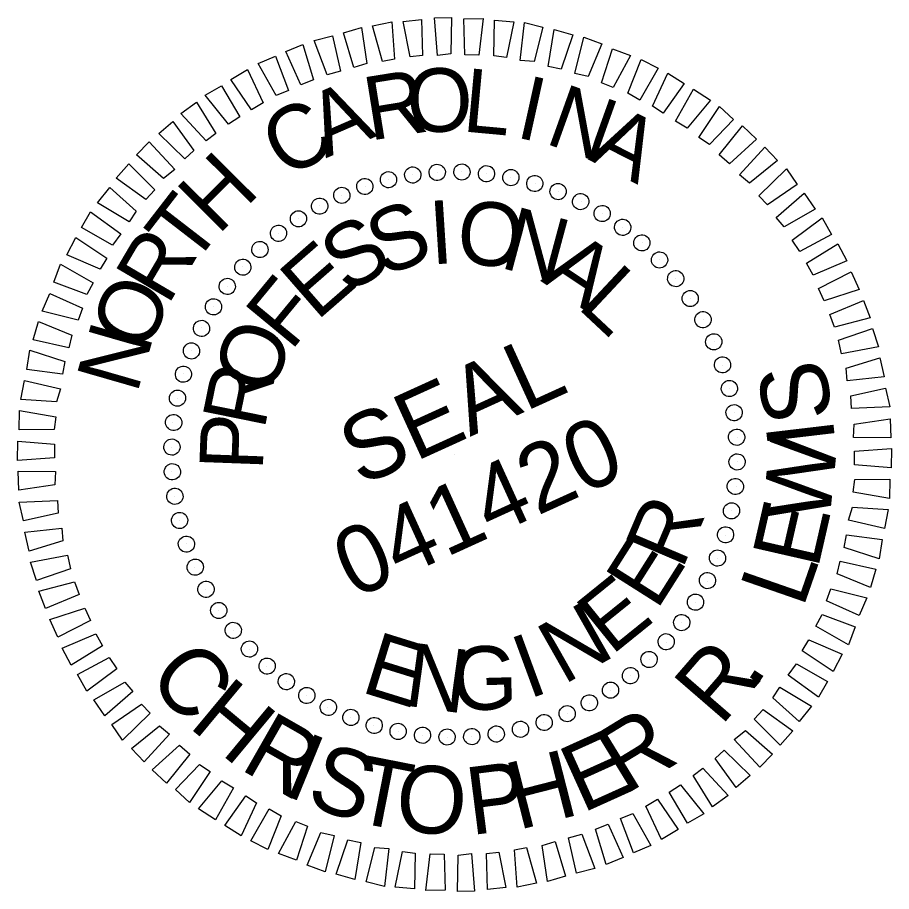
# Model space of a CAD drawing. Extents: x 2237908 to 2239894, y 658266 to 660035.
# Drawn here: x 2239756.3 to 2239833.9, y 659957.6 to 660035.2 of the extents above; entities that cross this region are included whole.
import ezdxf

# ---------------------------------------------------------------- set-up
doc = ezdxf.new("R2010")
doc.units = 0
doc.layers.add('Sheet PE Seal Cell', color=7, linetype='Continuous')

msp = doc.modelspace()

# ---------------------------------------------------------------- linework, layer by layer
at = {"layer": 'Sheet PE Seal Cell'}
for p, q in [((2239791.368, 660021.269), (2239791.368, 660021.269)), ((2239793.569, 660021.503), (2239793.569, 660021.503)), ((2239795.762, 660021.514), (2239795.762, 660021.514)), ((2239797.951, 660021.412), (2239797.951, 660021.412)), ((2239789.27, 660020.808), (2239789.27, 660020.808)), ((2239800.108, 660021.021), (2239800.108, 660021.021)), ((2239802.26, 660020.518), (2239802.26, 660020.518)), ((2239787.169, 660020.235), (2239787.169, 660020.235)), ((2239804.292, 660019.796), (2239804.292, 660019.796)), ((2239785.105, 660019.459), (2239785.105, 660019.459)), ((2239806.341, 660018.917), (2239806.341, 660018.917)), ((2239783.123, 660018.502), (2239783.123, 660018.502)), ((2239781.291, 660017.337), (2239781.291, 660017.337)), ((2239808.205, 660017.842), (2239808.205, 660017.842)), ((2239810.039, 660016.59), (2239810.039, 660016.59)), ((2239779.455, 660016.061), (2239779.455, 660016.061)), ((2239811.758, 660015.231), (2239811.758, 660015.231)), ((2239777.793, 660014.644), (2239777.793, 660014.644)), ((2239813.315, 660013.742), (2239813.315, 660013.742)), ((2239776.305, 660013.087), (2239776.305, 660013.087)), ((2239814.732, 660012.08), (2239814.732, 660012.08)), ((2239774.945, 660011.368), (2239774.945, 660011.368)), ((2239816.008, 660010.244), (2239816.008, 660010.244)), ((2239773.693, 660009.534), (2239773.693, 660009.534)), ((2239817.172, 660008.412), (2239817.172, 660008.412)), ((2239772.619, 660007.671), (2239772.619, 660007.671)), ((2239818.13, 660006.431), (2239818.13, 660006.431)), ((2239771.739, 660005.622), (2239771.739, 660005.622)), ((2239818.906, 660004.367), (2239818.906, 660004.367)), ((2239771.017, 660003.589), (2239771.017, 660003.589)), ((2239819.479, 660002.265), (2239819.479, 660002.265)), ((2239770.514, 660001.437), (2239770.514, 660001.437)), ((2239819.94, 660000.168), (2239819.94, 660000.168)), ((2239770.123, 659999.281), (2239770.123, 659999.281)), ((2239820.174, 659997.966), (2239820.174, 659997.966)), ((2239770.022, 659997.091), (2239770.022, 659997.091)), ((2239795.103, 659996.432), (2239795.103, 659996.432)), ((2239820.184, 659995.773), (2239820.184, 659995.773)), ((2239770.032, 659994.898), (2239770.032, 659994.898)), ((2239820.083, 659993.584), (2239820.083, 659993.584)), ((2239770.266, 659992.697), (2239770.266, 659992.697)), ((2239819.692, 659991.428), (2239819.692, 659991.428)), ((2239770.727, 659990.6), (2239770.727, 659990.6)), ((2239819.189, 659989.276), (2239819.189, 659989.276)), ((2239771.3, 659988.498), (2239771.3, 659988.498)), ((2239818.467, 659987.243), (2239818.467, 659987.243)), ((2239772.076, 659986.434), (2239772.076, 659986.434)), ((2239817.587, 659985.194), (2239817.587, 659985.194)), ((2239773.034, 659984.453), (2239773.034, 659984.453)), ((2239816.513, 659983.331), (2239816.513, 659983.331)), ((2239774.198, 659982.621), (2239774.198, 659982.621)), ((2239815.261, 659981.496), (2239815.261, 659981.496)), ((2239775.475, 659980.785), (2239775.475, 659980.785)), ((2239813.901, 659979.778), (2239813.901, 659979.778)), ((2239776.891, 659979.122), (2239776.891, 659979.122)), ((2239778.449, 659977.634), (2239778.449, 659977.634)), ((2239812.413, 659978.221), (2239812.413, 659978.221)), ((2239780.167, 659976.274), (2239780.167, 659976.274)), ((2239810.751, 659976.804), (2239810.751, 659976.804)), ((2239808.915, 659975.528), (2239808.915, 659975.528)), ((2239782.002, 659975.022), (2239782.002, 659975.022)), ((2239783.865, 659973.948), (2239783.865, 659973.948)), ((2239807.083, 659974.363), (2239807.083, 659974.363)), ((2239785.914, 659973.069), (2239785.914, 659973.069)), ((2239805.102, 659973.405), (2239805.102, 659973.405)), ((2239787.946, 659972.346), (2239787.946, 659972.346)), ((2239803.037, 659972.63), (2239803.037, 659972.63)), ((2239790.099, 659971.844), (2239790.099, 659971.844)), ((2239792.255, 659971.453), (2239792.255, 659971.453)), ((2239798.838, 659971.595), (2239798.838, 659971.595)), ((2239800.936, 659972.057), (2239800.936, 659972.057)), ((2239794.444, 659971.351), (2239794.444, 659971.351)), ((2239796.637, 659971.361), (2239796.637, 659971.361))]:
    msp.add_line(p, q, dxfattribs=at)
for points in [[(2239791.164, 660031.726), (2239790.561, 660034.858), (2239792.178, 660035.046), (2239792.264, 660031.843)], [(2239793.584, 660031.84), (2239793.324, 660035.183), (2239794.847, 660035.218), (2239794.776, 660031.998)], [(2239796.026, 660031.909), (2239795.94, 660035.111), (2239797.64, 660035.117), (2239797.255, 660031.864)], [(2239786.162, 660030.765), (2239785.244, 660033.864), (2239786.849, 660034.321), (2239787.316, 660031.127)], [(2239788.71, 660031.322), (2239787.817, 660034.487), (2239789.53, 660034.828), (2239789.769, 660031.53)], [(2239798.595, 660031.816), (2239798.642, 660034.969), (2239800.359, 660034.818), (2239799.709, 660031.664)], [(2239800.93, 660031.396), (2239801.32, 660034.761), (2239802.938, 660034.344), (2239802.179, 660031.306)], [(2239783.812, 660030.134), (2239782.646, 660033.175), (2239784.272, 660033.586), (2239784.987, 660030.45)], [(2239803.417, 660030.881), (2239803.96, 660034.151), (2239805.599, 660033.689), (2239804.572, 660030.638)], [(2239805.789, 660030.258), (2239806.576, 660033.474), (2239808.166, 660032.88), (2239806.964, 660029.97)], [(2239781.475, 660029.234), (2239780.127, 660032.192), (2239781.649, 660032.83), (2239782.587, 660029.686)], [(2239808.152, 660029.412), (2239809.134, 660032.442), (2239810.724, 660031.848), (2239809.167, 660028.995)], [(2239779.27, 660028.284), (2239777.695, 660031.138), (2239779.217, 660031.777), (2239780.383, 660028.736)], [(2239810.491, 660028.5), (2239811.651, 660031.501), (2239813.166, 660030.708), (2239811.543, 660027.88)], [(2239777.099, 660027.02), (2239775.271, 660029.704), (2239776.735, 660030.591), (2239778.128, 660027.654)], [(2239812.665, 660027.348), (2239814.023, 660030.274), (2239815.489, 660029.349), (2239813.605, 660026.732)], [(2239775.039, 660025.752), (2239772.984, 660028.332), (2239774.423, 660029.153), (2239776.069, 660026.386)], [(2239814.698, 660026.021), (2239816.321, 660028.849), (2239817.808, 660027.878), (2239815.749, 660025.401)], [(2239773.083, 660024.256), (2239770.822, 660026.687), (2239772.223, 660027.711), (2239773.935, 660024.919)], [(2239816.793, 660024.558), (2239818.615, 660027.312), (2239819.849, 660026.171), (2239817.733, 660023.943)], [(2239771.169, 660022.67), (2239768.878, 660024.923), (2239770.102, 660025.975), (2239771.979, 660023.424)], [(2239818.594, 660023.016), (2239820.657, 660025.605), (2239821.912, 660024.418), (2239819.506, 660022.223)], [(2239769.271, 660020.926), (2239766.886, 660023.026), (2239768.002, 660024.194), (2239770.284, 660021.717)], [(2239820.388, 660021.251), (2239822.624, 660023.699), (2239823.767, 660022.517), (2239821.278, 660020.503)], [(2239767.705, 660019.058), (2239765.088, 660020.943), (2239766.208, 660022.222), (2239768.519, 660019.924)], [(2239822.111, 660019.399), (2239824.546, 660021.772), (2239825.503, 660020.395), (2239822.865, 660018.589)], [(2239766.246, 660017.075), (2239763.443, 660018.764), (2239764.521, 660020.135), (2239766.861, 660018.015)], [(2239823.652, 660017.464), (2239826.125, 660019.635), (2239827.103, 660018.212), (2239824.361, 660016.633)], [(2239764.762, 660015.025), (2239762.021, 660016.578), (2239762.81, 660017.982), (2239765.514, 660016.027)], [(2239825.057, 660015.467), (2239827.724, 660017.451), (2239828.565, 660015.966), (2239825.737, 660014.458)], [(2239763.655, 660012.872), (2239760.703, 660014.164), (2239761.497, 660015.68), (2239764.25, 660013.857)], [(2239826.325, 660013.407), (2239829.117, 660015.119), (2239829.913, 660013.613), (2239826.914, 660012.356)], [(2239762.478, 660010.632), (2239759.564, 660011.722), (2239760.158, 660013.312), (2239763.052, 660011.663)], [(2239827.407, 660011.153), (2239830.302, 660012.637), (2239831.007, 660011.09), (2239827.905, 660010.061)], [(2239761.702, 660008.356), (2239758.532, 660009.164), (2239759.192, 660010.729), (2239762.098, 660009.415)], [(2239828.398, 660008.857), (2239831.397, 660010.114), (2239831.99, 660008.571), (2239828.805, 660007.724)], [(2239760.897, 660005.901), (2239757.723, 660006.597), (2239758.185, 660008.236), (2239761.161, 660007.01)], [(2239829.166, 660006.57), (2239832.202, 660007.623), (2239832.725, 660005.994), (2239829.436, 660005.374)], [(2239760.32, 660003.55), (2239757.159, 660003.977), (2239757.422, 660005.691), (2239760.518, 660004.684)], [(2239829.859, 660004.083), (2239832.846, 660005.005), (2239833.233, 660003.313), (2239829.931, 660002.962)], [(2239759.785, 660001.108), (2239756.615, 660001.312), (2239756.944, 660003.001), (2239760.14, 660002.259)], [(2239830.263, 660001.63), (2239833.354, 660002.324), (2239833.719, 660000.677), (2239830.335, 660000.508)], [(2239759.584, 659998.654), (2239756.473, 659998.61), (2239756.512, 660000.331), (2239759.736, 659999.767)], [(2239830.576, 659999.135), (2239833.77, 659999.601), (2239833.821, 659997.921), (2239830.511, 659997.951)], [(2239759.628, 659996.146), (2239756.33, 659995.908), (2239756.37, 659997.629), (2239759.627, 659997.355)], [(2239830.578, 659996.718), (2239833.876, 659996.957), (2239833.836, 659995.236), (2239830.579, 659995.51)], [(2239759.63, 659993.73), (2239756.436, 659993.263), (2239756.385, 659994.943), (2239759.695, 659994.913)], [(2239830.622, 659994.211), (2239833.734, 659994.255), (2239833.694, 659992.533), (2239830.47, 659993.097)], [(2239759.943, 659991.235), (2239756.853, 659990.541), (2239756.487, 659992.188), (2239759.872, 659992.356)], [(2239830.421, 659991.757), (2239833.591, 659991.553), (2239833.262, 659989.864), (2239830.067, 659990.606)], [(2239760.347, 659988.781), (2239757.36, 659987.86), (2239756.973, 659989.552), (2239760.275, 659989.903)], [(2239829.886, 659989.315), (2239833.048, 659988.887), (2239832.784, 659987.174), (2239829.688, 659988.181)], [(2239761.04, 659986.295), (2239758.004, 659985.241), (2239757.481, 659986.871), (2239760.77, 659987.491)], [(2239829.309, 659986.964), (2239832.483, 659986.267), (2239832.021, 659984.628), (2239829.045, 659985.854)], [(2239761.808, 659984.008), (2239758.809, 659982.751), (2239758.216, 659984.294), (2239761.401, 659985.141)], [(2239828.504, 659984.509), (2239831.675, 659983.701), (2239831.014, 659982.136), (2239828.108, 659983.449)], [(2239762.799, 659981.712), (2239759.904, 659980.228), (2239759.199, 659981.775), (2239762.301, 659982.804)], [(2239827.728, 659982.232), (2239830.643, 659981.143), (2239830.048, 659979.553), (2239827.154, 659981.201)], [(2239763.881, 659979.458), (2239761.09, 659977.746), (2239760.294, 659979.252), (2239763.293, 659980.508)], [(2239826.551, 659979.993), (2239829.503, 659978.7), (2239828.71, 659977.185), (2239825.956, 659979.007)], [(2239765.149, 659977.398), (2239762.482, 659975.414), (2239761.641, 659976.898), (2239764.47, 659978.407)], [(2239825.444, 659977.84), (2239828.185, 659976.286), (2239827.396, 659974.883), (2239824.692, 659976.838)], [(2239766.554, 659975.401), (2239764.081, 659973.23), (2239763.104, 659974.653), (2239765.846, 659976.232)], [(2239823.96, 659975.79), (2239826.764, 659974.1), (2239825.685, 659972.73), (2239823.345, 659974.85)], [(2239768.095, 659973.466), (2239765.66, 659971.092), (2239764.703, 659972.469), (2239767.341, 659974.276)], [(2239822.502, 659973.807), (2239825.119, 659971.922), (2239823.998, 659970.642), (2239821.687, 659972.941)], [(2239769.818, 659971.613), (2239767.582, 659969.166), (2239766.439, 659970.348), (2239768.928, 659972.362)], [(2239820.935, 659971.939), (2239823.321, 659969.839), (2239822.204, 659968.671), (2239819.922, 659971.148)], [(2239771.612, 659969.848), (2239769.549, 659967.26), (2239768.294, 659968.446), (2239770.701, 659970.642)], [(2239819.037, 659970.195), (2239821.328, 659967.942), (2239820.104, 659966.89), (2239818.227, 659969.441)], [(2239773.413, 659968.306), (2239771.591, 659965.553), (2239770.357, 659966.694), (2239772.473, 659968.922)], [(2239817.123, 659968.608), (2239819.385, 659966.177), (2239817.983, 659965.154), (2239816.271, 659967.945)], [(2239775.508, 659966.844), (2239773.885, 659964.016), (2239772.398, 659964.987), (2239774.457, 659967.463)], [(2239815.167, 659967.113), (2239817.222, 659964.532), (2239815.783, 659963.712), (2239814.137, 659966.479)], [(2239777.541, 659965.517), (2239776.183, 659962.59), (2239774.717, 659963.516), (2239776.602, 659966.133)], [(2239813.108, 659965.844), (2239814.935, 659963.161), (2239813.471, 659962.274), (2239812.078, 659965.21)], [(2239779.715, 659964.365), (2239778.555, 659961.363), (2239777.04, 659962.157), (2239778.663, 659964.984)], [(2239810.936, 659964.58), (2239812.511, 659961.727), (2239810.989, 659961.088), (2239809.824, 659964.128)], [(2239782.054, 659963.452), (2239781.072, 659960.422), (2239779.482, 659961.017), (2239781.04, 659963.869)], [(2239784.417, 659962.606), (2239783.63, 659959.39), (2239782.041, 659959.985), (2239783.242, 659962.895)], [(2239808.732, 659963.631), (2239810.079, 659960.673), (2239808.557, 659960.034), (2239807.619, 659963.179)], [(2239786.789, 659961.984), (2239786.246, 659958.714), (2239784.607, 659959.176), (2239785.634, 659962.227)], [(2239806.394, 659962.73), (2239807.56, 659959.69), (2239805.934, 659959.279), (2239805.22, 659962.415)], [(2239789.277, 659961.469), (2239788.887, 659958.104), (2239787.268, 659958.521), (2239788.027, 659961.559)], [(2239801.496, 659961.542), (2239802.389, 659958.378), (2239800.676, 659958.037), (2239800.437, 659961.334)], [(2239804.045, 659962.099), (2239804.962, 659959.001), (2239803.357, 659958.544), (2239802.89, 659961.738)], [(2239791.611, 659961.049), (2239791.564, 659957.896), (2239789.847, 659958.047), (2239790.498, 659961.201)], [(2239794.181, 659960.956), (2239794.266, 659957.753), (2239792.566, 659957.748), (2239792.952, 659961)], [(2239796.622, 659961.025), (2239796.882, 659957.681), (2239795.359, 659957.647), (2239795.43, 659960.866)], [(2239799.043, 659961.139), (2239799.646, 659958.007), (2239798.028, 659957.819), (2239797.942, 659961.022)]]:
    msp.add_lwpolyline(points, close=True, dxfattribs=at)
for centre, major_axis in [((2239791.397, 660021.237), (-0.106, 0.712)), ((2239793.573, 660021.466), (-0.044, 0.719)), ((2239795.761, 660021.504), (0.019, 0.72)), ((2239797.943, 660021.351), (0.082, 0.715)), ((2239789.249, 660020.82), (-0.168, 0.7)), ((2239800.104, 660021.009), (0.144, 0.706)), ((2239802.227, 660020.479), (0.205, 0.69)), ((2239787.146, 660020.217), (-0.228, 0.683)), ((2239804.296, 660019.767), (0.264, 0.67)), ((2239785.103, 660019.433), (-0.287, 0.66)), ((2239806.295, 660018.877), (0.321, 0.644)), ((2239783.137, 660018.474), (-0.344, 0.633)), ((2239781.261, 660017.347), (-0.397, 0.6)), ((2239808.208, 660017.816), (0.376, 0.614)), ((2239810.022, 660016.593), (0.428, 0.579)), ((2239779.491, 660016.061), (-0.448, 0.563)), ((2239811.722, 660015.216), (0.477, 0.539)), ((2239777.84, 660014.625), (-0.496, 0.522)), ((2239813.296, 660013.696), (0.522, 0.496)), ((2239776.32, 660013.052), (-0.539, 0.477)), ((2239814.731, 660012.044), (0.563, 0.448)), ((2239774.943, 660011.351), (-0.579, 0.428)), ((2239816.017, 660010.274), (0.6, 0.397)), ((2239773.719, 660009.537), (-0.614, 0.376)), ((2239817.144, 660008.399), (0.633, 0.344)), ((2239772.659, 660007.624), (-0.644, 0.321)), ((2239818.103, 660006.432), (0.66, 0.287)), ((2239771.769, 660005.625), (-0.67, 0.264)), ((2239818.887, 660004.389), (0.683, 0.228)), ((2239771.056, 660003.556), (-0.69, 0.205)), ((2239819.49, 660002.286), (0.7, 0.168)), ((2239770.527, 660001.433), (-0.706, 0.144)), ((2239819.908, 660000.139), (0.712, 0.106)), ((2239770.184, 659999.272), (-0.715, 0.082)), ((2239820.136, 659997.963), (0.719, 0.044)), ((2239770.032, 659997.09), (-0.72, 0.019)), ((2239820.174, 659995.775), (0.72, -0.019)), ((2239770.07, 659994.902), (-0.719, -0.044)), ((2239820.022, 659993.592), (0.715, -0.082)), ((2239770.298, 659992.726), (-0.712, -0.106)), ((2239819.679, 659991.431), (0.706, -0.144)), ((2239770.716, 659990.578), (-0.7, -0.168)), ((2239819.15, 659989.308), (0.69, -0.205)), ((2239771.319, 659988.475), (-0.683, -0.228)), ((2239818.438, 659987.24), (0.67, -0.264)), ((2239772.103, 659986.433), (-0.66, -0.287)), ((2239817.548, 659985.241), (0.644, -0.321)), ((2239773.062, 659984.466), (-0.633, -0.344)), ((2239816.487, 659983.327), (0.614, -0.376)), ((2239774.189, 659982.591), (-0.6, -0.397)), ((2239815.263, 659981.513), (0.579, -0.428)), ((2239775.475, 659980.82), (-0.563, -0.448)), ((2239776.91, 659979.169), (-0.522, -0.496)), ((2239813.886, 659979.813), (0.539, -0.477)), ((2239778.484, 659977.649), (-0.477, -0.539)), ((2239812.366, 659978.239), (0.496, -0.522)), ((2239780.184, 659976.272), (-0.428, -0.579)), ((2239810.715, 659976.804), (0.448, -0.563)), ((2239808.945, 659975.518), (0.397, -0.6)), ((2239781.998, 659975.049), (-0.376, -0.614)), ((2239783.912, 659973.988), (-0.321, -0.644)), ((2239807.069, 659974.391), (0.344, -0.633)), ((2239785.91, 659973.098), (-0.264, -0.67)), ((2239805.103, 659973.432), (0.287, -0.66)), ((2239787.979, 659972.385), (-0.205, -0.69)), ((2239803.06, 659972.648), (0.228, -0.683)), ((2239790.102, 659971.856), (-0.144, -0.706)), ((2239792.263, 659971.514), (-0.082, -0.715)), ((2239798.809, 659971.628), (0.106, -0.712)), ((2239800.957, 659972.045), (0.168, -0.7)), ((2239794.446, 659971.361), (-0.019, -0.72)), ((2239796.633, 659971.399), (0.044, -0.719))]:
    msp.add_ellipse(centre, major_axis=major_axis, ratio=0.999708, dxfattribs=at)

# ---------------------------------------------------------------- texts
for s, height, rotation, p in [('R', 5.638, 9.11904, (2239787.583, 660024.27)), ('O', 5.638, 1.91911, (2239790.942, 660024.977)), ('L', 5.638, 354.71882, (2239795.713, 660025.118)), ('I', 5.638, 347.51808, (2239800.394, 660024.613)), ('A', 5.638, 23.51826, (2239783.678, 660022.71)), ('N', 5.639, 340.31685, (2239802.993, 660024.094)), ('C', 5.638, 30.71781, (2239780.208, 660020.8)), ('A', 5.639, 333.1151, (2239806.901, 660022.633)), ('H', 5.638, 45.11742, (2239774.122, 660015.828)), ('T', 5.638, 52.31772, (2239771.848, 660012.979)), ('S', 5.638, 22.39834, (2239788.823, 660012.143)), ('I', 5.638, 3.68755, (2239793.026, 660013.289)), ('O', 5.638, 354.33143, (2239795.137, 660013.481)), ('N', 5.639, 344.97455, (2239799.014, 660013.05)), ('S', 5.638, 31.75355, (2239785.568, 660010.604)), ('R', 5.639, 59.51845, (2239769.667, 660009.567)), ('E', 5.638, 41.10901, (2239782.864, 660008.218)), ('A', 5.639, 326.25821, (2239802.686, 660011.866)), ('L', 5.639, 316.89879, (2239805.891, 660009.535)), ('O', 5.639, 66.71968, (2239767.813, 660005.316)), ('F', 5.638, 50.46498, (2239780.574, 660005.526)), ('N', 5.639, 73.92144, (2239766.922, 660001.723)), ('O', 5.639, 69.17918, (2239778.795, 660001.474)), ('SEAL', 5.9982, 24.49794, (2239786.744, 659993.556)), ('R', 5.639, 78.53759, (2239778.218, 659998.519)), ('S', 5.998, 100.55241, (2239828.75, 659999.834)), ('P', 5.639, 87.89683, (2239778.089, 659994.943)), ('041420', 5.9982, 24.49794, (2239786.194, 659983.572)), ('I', 5.998, 96.75046, (2239828.901, 659997.595)), ('W', 5.998, 84.21639, (2239828.348, 659990.233)), ('R', 5.639, 66.97935, (2239815.294, 659986.127)), ('E', 5.998, 77.10705, (2239827.325, 659986.166)), ('E', 5.638, 57.62203, (2239813.038, 659982.516)), ('L', 5.998, 70.83229, (2239826.01, 659982.705)), ('E', 5.638, 38.9097, (2239809.024, 659978.544)), ('N', 5.638, 29.55433, (2239804.768, 659975.946)), ('E', 5.638, 342.77483, (2239786.669, 659975.391)), ('I', 5.638, 20.19914, (2239801.658, 659974.693)), ('C', 5.998, 310.69992, (2239767.716, 659976.593)), ('N', 5.639, 352.1319, (2239790.518, 659974.178)), ('G', 5.638, 1.48818, (2239794.909, 659973.706)), ('R', 5.998, 49.11789, (2239818.738, 659972.245)), ('.', 5.998, 56.59815, (2239821.686, 659975.527)), ('H', 5.998, 320.28207, (2239771.401, 659972.311)), ('R', 5.998, 330.26605, (2239775.942, 659968.567)), ('R', 5.998, 31.43728, (2239810.276, 659966.209)), ('I', 5.998, 337.74631, (2239779.732, 659966.309)), ('E', 5.998, 24.32794, (2239806.419, 659964.563)), ('S', 5.998, 341.54826, (2239781.764, 659965.356)), ('H', 5.998, 14.34395, (2239800.722, 659963.084)), ('T', 5.998, 348.87397, (2239785.835, 659963.909)), ('P', 5.998, 7.23461, (2239796.551, 659962.645)), ('O', 5.998, 355.67421, (2239789.751, 659963.04))]:
    msp.add_text(s, height=height, rotation=rotation, dxfattribs=at).set_placement(p)

doc.saveas('drawing.dxf')
